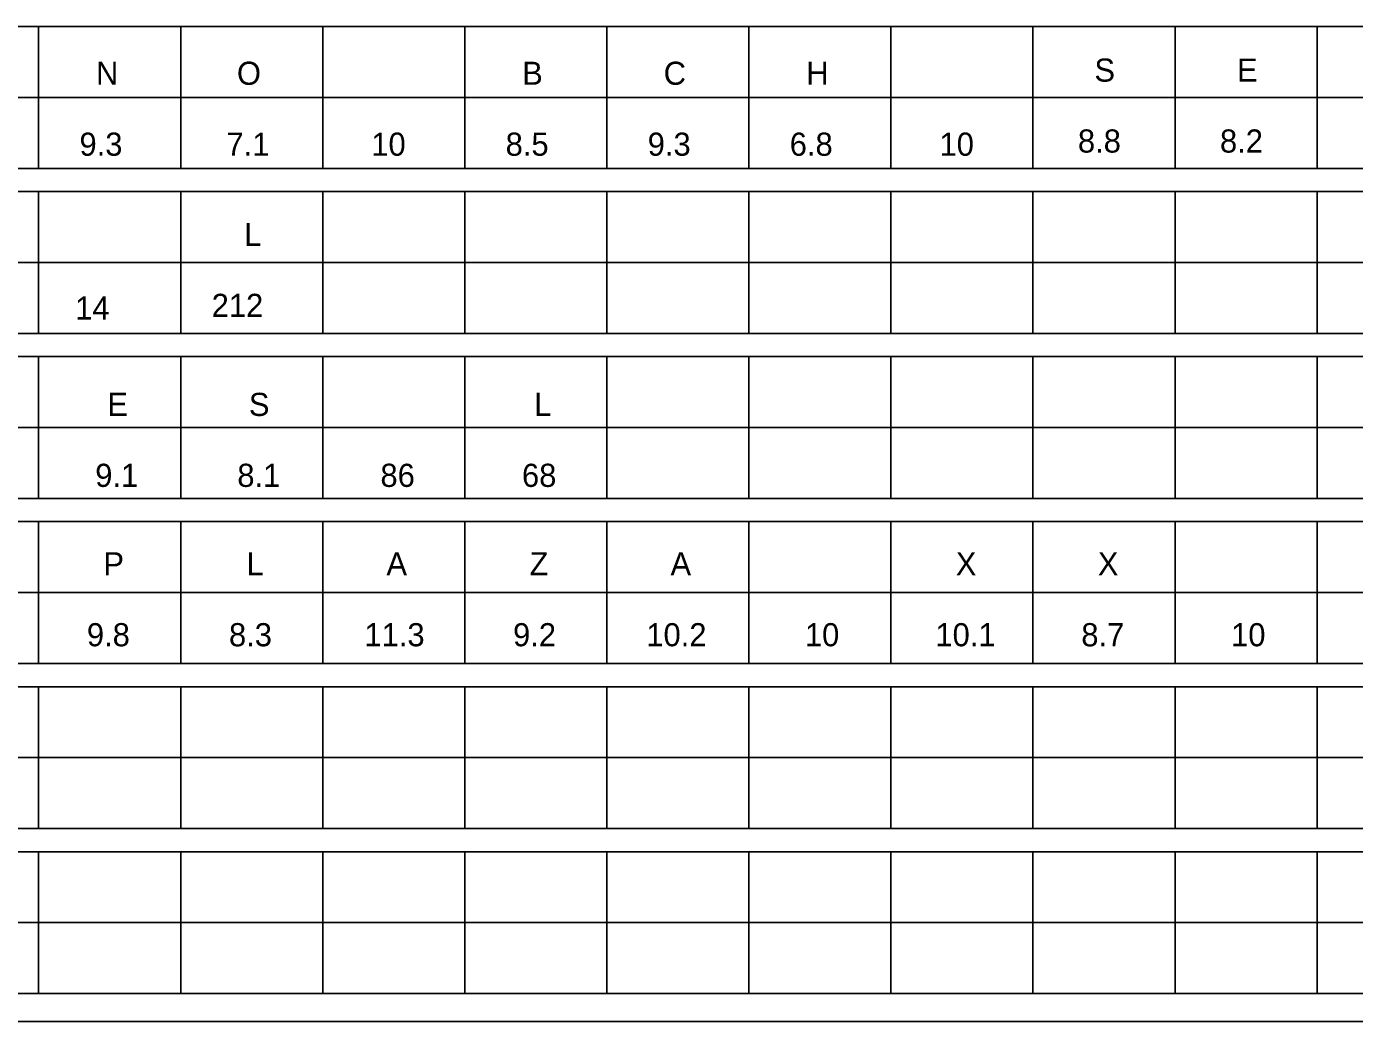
# Model space of a CAD drawing. Extents: x 17890484 to 17890754, y 17897495 to 17897992.
# Drawn here: x 17890512.7 to 17890540.84, y 17897550.98 to 17897572.06 of the extents above; entities that cross this region are included whole.
import ezdxf

# ---------------------------------------------------------------- set-up
doc = ezdxf.new("R2010")
doc.units = 0
doc.layers.add('GSSign', color=7, linetype='Continuous')
doc.layers.add('SheetLinesMisc2_dp', color=7, linetype='Continuous')

msp = doc.modelspace()

# ---------------------------------------------------------------- linework, layer by layer
at = {"layer": 'SheetLinesMisc2_dp'}
for p, q in [((17890490.134, 17897572.057), (17890564.13, 17897572.057)), ((17890512.958, 17897572.057), (17890512.958, 17897569.05)), ((17890515.968, 17897572.057), (17890515.968, 17897569.05)), ((17890518.978, 17897572.057), (17890518.978, 17897569.05)), ((17890521.988, 17897572.057), (17890521.988, 17897569.05)), ((17890524.999, 17897572.057), (17890524.999, 17897569.05)), ((17890528.008, 17897572.057), (17890528.008, 17897569.05)), ((17890531.018, 17897572.057), (17890531.018, 17897569.05)), ((17890534.028, 17897572.057), (17890534.028, 17897569.05)), ((17890537.039, 17897572.057), (17890537.039, 17897569.05)), ((17890540.049, 17897572.057), (17890540.049, 17897569.05)), ((17890490.134, 17897570.554), (17890564.13, 17897570.554)), ((17890490.134, 17897569.05), (17890564.13, 17897569.05)), ((17890490.134, 17897568.56), (17890564.13, 17897568.56)), ((17890512.958, 17897568.56), (17890512.958, 17897565.555)), ((17890515.968, 17897568.56), (17890515.968, 17897565.555)), ((17890518.978, 17897568.56), (17890518.978, 17897565.555)), ((17890521.988, 17897568.56), (17890521.988, 17897565.555)), ((17890524.999, 17897568.56), (17890524.999, 17897565.555)), ((17890528.008, 17897568.56), (17890528.008, 17897565.555)), ((17890531.018, 17897568.56), (17890531.018, 17897565.555)), ((17890534.028, 17897568.56), (17890534.028, 17897565.555)), ((17890537.039, 17897568.56), (17890537.039, 17897565.555)), ((17890540.049, 17897568.56), (17890540.049, 17897565.555)), ((17890490.134, 17897567.057), (17890564.13, 17897567.058)), ((17890490.134, 17897565.555), (17890564.13, 17897565.555)), ((17890490.134, 17897565.064), (17890564.13, 17897565.064)), ((17890512.958, 17897565.064), (17890512.958, 17897562.058)), ((17890515.968, 17897565.064), (17890515.968, 17897562.058)), ((17890518.978, 17897565.064), (17890518.978, 17897562.058)), ((17890521.988, 17897565.064), (17890521.988, 17897562.058)), ((17890524.999, 17897565.064), (17890524.999, 17897562.058)), ((17890528.008, 17897565.064), (17890528.008, 17897562.058)), ((17890531.018, 17897565.064), (17890531.018, 17897562.058)), ((17890534.028, 17897565.064), (17890534.028, 17897562.058)), ((17890537.039, 17897565.064), (17890537.039, 17897562.058)), ((17890540.049, 17897565.064), (17890540.049, 17897562.058)), ((17890490.134, 17897563.561), (17890564.13, 17897563.561)), ((17890490.134, 17897562.058), (17890564.13, 17897562.058)), ((17890490.134, 17897561.568), (17890564.13, 17897561.568)), ((17890512.958, 17897561.568), (17890512.958, 17897558.562)), ((17890515.968, 17897561.568), (17890515.968, 17897558.562)), ((17890518.978, 17897561.568), (17890518.978, 17897558.562)), ((17890521.988, 17897561.568), (17890521.988, 17897558.562)), ((17890524.999, 17897561.568), (17890524.999, 17897558.562)), ((17890528.008, 17897561.568), (17890528.008, 17897558.562)), ((17890531.018, 17897561.568), (17890531.018, 17897558.562)), ((17890534.028, 17897561.568), (17890534.028, 17897558.562)), ((17890537.039, 17897561.568), (17890537.039, 17897558.562)), ((17890540.049, 17897561.568), (17890540.049, 17897558.562)), ((17890490.134, 17897560.065), (17890564.13, 17897560.065)), ((17890490.134, 17897558.562), (17890564.13, 17897558.562)), ((17890490.134, 17897558.071), (17890564.13, 17897558.071)), ((17890512.958, 17897558.071), (17890512.958, 17897555.065)), ((17890515.968, 17897558.071), (17890515.968, 17897555.065)), ((17890518.978, 17897558.071), (17890518.978, 17897555.065)), ((17890521.988, 17897558.071), (17890521.988, 17897555.065)), ((17890524.999, 17897558.071), (17890524.999, 17897555.065)), ((17890528.008, 17897558.071), (17890528.008, 17897555.065)), ((17890531.018, 17897558.071), (17890531.018, 17897555.065)), ((17890534.028, 17897558.071), (17890534.028, 17897555.065)), ((17890537.039, 17897558.071), (17890537.039, 17897555.065)), ((17890540.049, 17897558.071), (17890540.049, 17897555.065)), ((17890490.134, 17897556.569), (17890564.13, 17897556.569)), ((17890490.134, 17897555.065), (17890564.13, 17897555.065)), ((17890490.134, 17897554.575), (17890564.13, 17897554.575)), ((17890512.958, 17897554.575), (17890512.958, 17897551.569)), ((17890515.968, 17897554.575), (17890515.968, 17897551.569)), ((17890518.978, 17897554.575), (17890518.978, 17897551.569)), ((17890521.988, 17897554.575), (17890521.988, 17897551.569)), ((17890524.999, 17897554.575), (17890524.999, 17897551.569)), ((17890528.008, 17897554.575), (17890528.008, 17897551.569)), ((17890531.018, 17897554.575), (17890531.018, 17897551.569)), ((17890534.028, 17897554.575), (17890534.028, 17897551.569)), ((17890537.039, 17897554.575), (17890537.039, 17897551.569)), ((17890540.049, 17897554.575), (17890540.049, 17897551.569)), ((17890490.134, 17897553.073), (17890564.13, 17897553.073)), ((17890490.134, 17897551.569), (17890564.13, 17897551.569)), ((17890489.413, 17897550.979), (17890564.641, 17897550.979))]:
    msp.add_line(p, q, dxfattribs=at)

# ---------------------------------------------------------------- texts
at = {"layer": 'GSSign'}
for s, height, p in [('N', 0.49, (17890514.173, 17897570.823)), ('O', 0.49, (17890517.16, 17897570.823)), ('B', 0.49, (17890523.204, 17897570.823)), ('C', 0.49, (17890526.203, 17897570.823)), ('H', 0.49, (17890529.225, 17897570.823)), ('S', 0.49, (17890535.331, 17897570.89)), ('E', 0.49, (17890538.353, 17897570.89)), ('9.3', 0.4902, (17890513.823, 17897569.32)), ('7.1', 0.4902, (17890516.938, 17897569.32)), ('10', 0.4902, (17890520.007, 17897569.32)), ('8.5', 0.4902, (17890522.854, 17897569.32)), ('9.3', 0.4902, (17890525.864, 17897569.32)), ('6.8', 0.4902, (17890528.874, 17897569.32)), ('10', 0.4902, (17890532.048, 17897569.32)), ('8.8', 0.4902, (17890534.981, 17897569.387)), ('8.2', 0.4902, (17890537.991, 17897569.387)), ('L', 0.49, (17890517.312, 17897567.408)), ('14', 0.4902, (17890513.732, 17897565.848)), ('212', 0.4902, (17890516.624, 17897565.905)), ('E', 0.49, (17890514.414, 17897563.807)), ('S', 0.49, (17890517.413, 17897563.807)), ('L', 0.49, (17890523.457, 17897563.807)), ('9.1', 0.4902, (17890514.157, 17897562.304)), ('8.1', 0.4902, (17890517.168, 17897562.304)), ('86', 0.4902, (17890520.201, 17897562.304)), ('68', 0.4902, (17890523.2, 17897562.304)), ('P', 0.49, (17890514.33, 17897560.43)), ('L', 0.49, (17890517.364, 17897560.43)), ('A', 0.49, (17890520.328, 17897560.43)), ('Z', 0.49, (17890523.361, 17897560.43)), ('A', 0.49, (17890526.348, 17897560.43)), ('X', 0.49, (17890532.393, 17897560.43)), ('X', 0.49, (17890535.403, 17897560.43)), ('9.8', 0.4902, (17890513.98, 17897558.927)), ('8.3', 0.4902, (17890516.991, 17897558.927)), ('11.3', 0.4902, (17890519.861, 17897558.927)), ('9.2', 0.4902, (17890523.011, 17897558.927)), ('10.2', 0.4902, (17890525.835, 17897558.927)), ('10', 0.4902, (17890529.195, 17897558.927)), ('10.1', 0.4902, (17890531.961, 17897558.927)), ('8.7', 0.4902, (17890535.053, 17897558.927)), ('10', 0.4902, (17890538.227, 17897558.927))]:
    msp.add_text(s, height=height, dxfattribs=at).set_placement(p)

doc.saveas('drawing.dxf')
